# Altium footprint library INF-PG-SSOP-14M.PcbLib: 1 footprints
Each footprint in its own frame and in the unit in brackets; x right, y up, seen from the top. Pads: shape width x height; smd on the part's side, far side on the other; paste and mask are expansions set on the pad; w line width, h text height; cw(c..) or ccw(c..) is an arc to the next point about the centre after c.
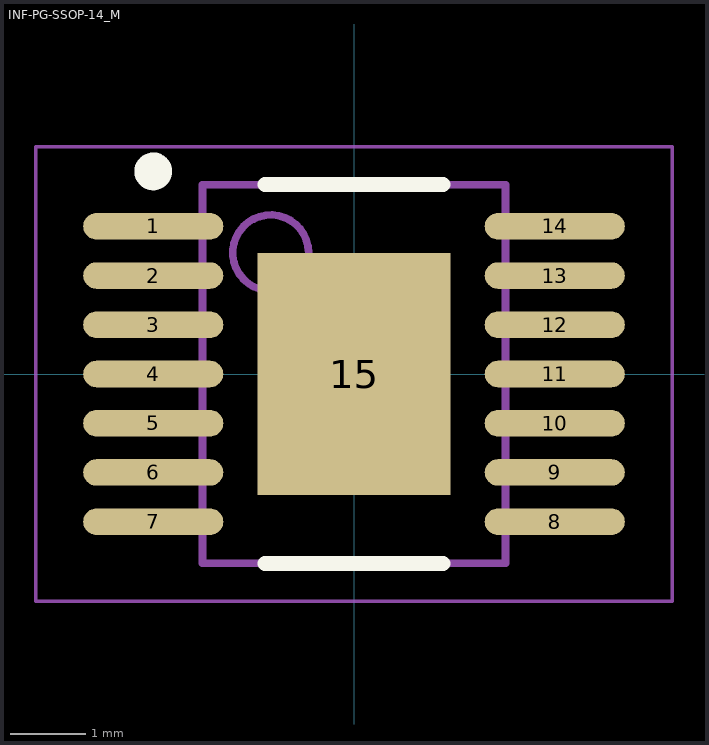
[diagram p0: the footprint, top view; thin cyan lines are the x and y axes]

## INF-PG-SSOP-14_M [mm] "SOP, 14-Leads, Body 4.9x3.9mm, Pitch 0.65mm, Thermal Pad 3.2x2.55mm, IPC Low Density"
height 1.7
pads (15):
  oval 1.85x0.35 smd: 1(-2.65,1.95) 2(-2.65,1.3) 3(-2.65,0.65) 4(-2.65,0) 5(-2.65,-0.65) 6(-2.65,-1.3) 7(-2.65,-1.95) 8(2.65,-1.95) 9(2.65,-1.3) 10(2.65,-0.65) 11(2.65,0) 12(2.65,0.65) 13(2.65,1.3) 14(2.65,1.95)
  rect 2.55x3.2 smd: 15(0,0)
Top Overlay:
  circle w0.25: c-2.65,2.675 r0.125
  lines w0.2: -1.175,-2.5 1.175,-2.5 ; -1.175,2.5 1.175,2.5
Mechanical 13:
  circle w0.1: c-1.1,1.6 r0.5
  lines w0.1: -2,-2.5 2,-2.5 2,2.5 -2,2.5 -2,-2.5
Mechanical 15:
  lines w0.05: -4.2,-3 4.2,-3 4.2,3 -4.2,3 -4.2,-3
  lines w0.1: -0.5,0 0.5,0 ; 0,-0.5 0,0.5
3D body: height 1.7, standoff 0, extent -2,-2.5 2,2.5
